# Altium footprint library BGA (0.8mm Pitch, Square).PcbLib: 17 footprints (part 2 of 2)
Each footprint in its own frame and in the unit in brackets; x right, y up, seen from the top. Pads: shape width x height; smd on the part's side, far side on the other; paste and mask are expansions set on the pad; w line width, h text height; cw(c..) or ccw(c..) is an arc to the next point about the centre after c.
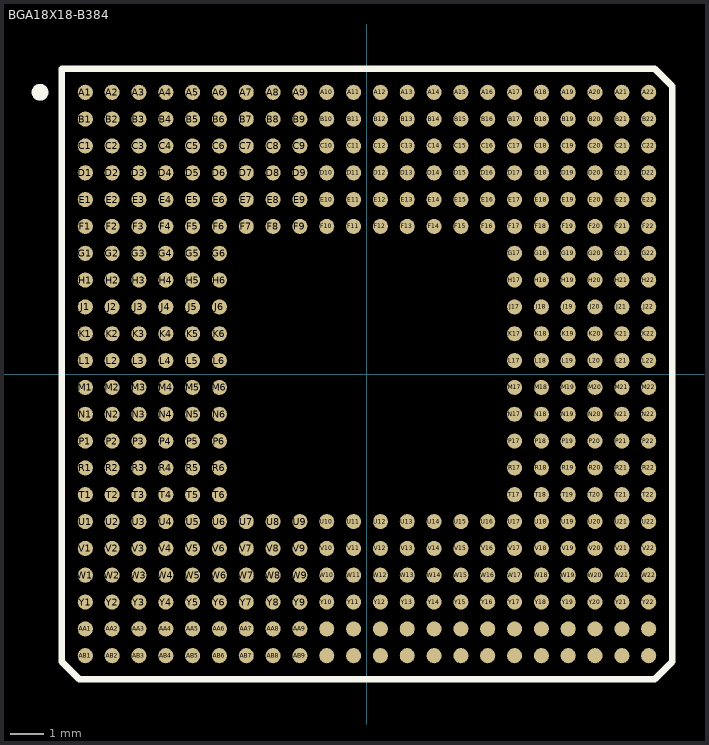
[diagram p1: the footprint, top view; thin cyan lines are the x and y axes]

## BGA18X18-B384 [mm]
pads (384):
  round 0.45 smd: A1(-8.4,8.4) A2(-7.6,8.4) A3(-6.8,8.4) A4(-6,8.4) A5(-5.2,8.4) A6(-4.4,8.4) A7(-3.6,8.4) A8(-2.8,8.4) A9(-2,8.4) A10(-1.2,8.4) A11(-0.4,8.4) A12(0.4,8.4) A13(1.2,8.4) A14(2,8.4) A15(2.8,8.4) A16(3.6,8.4) A17(4.4,8.4) A18(5.2,8.4) A19(6,8.4) A20(6.8,8.4) A21(7.6,8.4) A22(8.4,8.4) AA1(-8.4,-7.6) AA2(-7.6,-7.6) AA3(-6.8,-7.6) AA4(-6,-7.6) AA5(-5.2,-7.6) AA6(-4.4,-7.6) AA7(-3.6,-7.6) AA8(-2.8,-7.6) AA9(-2,-7.6) AA10(-1.2,-7.6) AA11(-0.4,-7.6) AA12(0.4,-7.6) AA13(1.2,-7.6) AA14(2,-7.6) AA15(2.8,-7.6) AA16(3.6,-7.6) AA17(4.4,-7.6) AA18(5.2,-7.6) AA19(6,-7.6) AA20(6.8,-7.6) AA21(7.6,-7.6) AA22(8.4,-7.6) AB1(-8.4,-8.4) AB2(-7.6,-8.4) AB3(-6.8,-8.4) AB4(-6,-8.4) AB5(-5.2,-8.4) AB6(-4.4,-8.4) AB7(-3.6,-8.4) AB8(-2.8,-8.4) AB9(-2,-8.4) AB10(-1.2,-8.4) AB11(-0.4,-8.4) AB12(0.4,-8.4) AB13(1.2,-8.4) AB14(2,-8.4) AB15(2.8,-8.4) AB16(3.6,-8.4) AB17(4.4,-8.4) AB18(5.2,-8.4) AB19(6,-8.4) AB20(6.8,-8.4) AB21(7.6,-8.4) AB22(8.4,-8.4) B1(-8.4,7.6) B2(-7.6,7.6) B3(-6.8,7.6) B4(-6,7.6) B5(-5.2,7.6) B6(-4.4,7.6) B7(-3.6,7.6) B8(-2.8,7.6) B9(-2,7.6) B10(-1.2,7.6) B11(-0.4,7.6) B12(0.4,7.6) B13(1.2,7.6) B14(2,7.6) B15(2.8,7.6) B16(3.6,7.6) B17(4.4,7.6) B18(5.2,7.6) B19(6,7.6) B20(6.8,7.6) B21(7.6,7.6) B22(8.4,7.6) C1(-8.4,6.8) C2(-7.6,6.8) C3(-6.8,6.8) C4(-6,6.8) C5(-5.2,6.8) C6(-4.4,6.8) C7(-3.6,6.8) C8(-2.8,6.8) C9(-2,6.8) C10(-1.2,6.8) C11(-0.4,6.8) C12(0.4,6.8) C13(1.2,6.8) C14(2,6.8) C15(2.8,6.8) C16(3.6,6.8) C17(4.4,6.8) C18(5.2,6.8) C19(6,6.8) C20(6.8,6.8) C21(7.6,6.8) C22(8.4,6.8) D1(-8.4,6) D2(-7.6,6) D3(-6.8,6) D4(-6,6) D5(-5.2,6) D6(-4.4,6) D7(-3.6,6) D8(-2.8,6) D9(-2,6) D10(-1.2,6) D11(-0.4,6) D12(0.4,6) D13(1.2,6) D14(2,6) D15(2.8,6) D16(3.6,6) D17(4.4,6) D18(5.2,6) D19(6,6) D20(6.8,6) D21(7.6,6) D22(8.4,6) E1(-8.4,5.2) E2(-7.6,5.2) E3(-6.8,5.2) E4(-6,5.2) E5(-5.2,5.2) E6(-4.4,5.2) E7(-3.6,5.2) E8(-2.8,5.2) E9(-2,5.2) E10(-1.2,5.2) E11(-0.4,5.2) E12(0.4,5.2) E13(1.2,5.2) E14(2,5.2) E15(2.8,5.2) E16(3.6,5.2) E17(4.4,5.2) E18(5.2,5.2) E19(6,5.2) E20(6.8,5.2) E21(7.6,5.2) E22(8.4,5.2) F1(-8.4,4.4) F2(-7.6,4.4) F3(-6.8,4.4) F4(-6,4.4) F5(-5.2,4.4) F6(-4.4,4.4) F7(-3.6,4.4) F8(-2.8,4.4) F9(-2,4.4) F10(-1.2,4.4) F11(-0.4,4.4) F12(0.4,4.4) F13(1.2,4.4) F14(2,4.4) F15(2.8,4.4) F16(3.6,4.4) F17(4.4,4.4) F18(5.2,4.4) F19(6,4.4) F20(6.8,4.4) F21(7.6,4.4) F22(8.4,4.4) G1(-8.4,3.6) G2(-7.6,3.6) G3(-6.8,3.6) G4(-6,3.6) G5(-5.2,3.6) G6(-4.4,3.6) G17(4.4,3.6) G18(5.2,3.6) G19(6,3.6) G20(6.8,3.6) G21(7.6,3.6) G22(8.4,3.6) H1(-8.4,2.8) H2(-7.6,2.8) H3(-6.8,2.8) H4(-6,2.8) H5(-5.2,2.8) H6(-4.4,2.8) H17(4.4,2.8) H18(5.2,2.8) H19(6,2.8) H20(6.8,2.8) H21(7.6,2.8) H22(8.4,2.8) J1(-8.4,2) J2(-7.6,2) J3(-6.8,2) J4(-6,2) J5(-5.2,2) J6(-4.4,2) J17(4.4,2) J18(5.2,2) J19(6,2) J20(6.8,2) J21(7.6,2) J22(8.4,2) K1(-8.4,1.2) K2(-7.6,1.2) K3(-6.8,1.2) K4(-6,1.2) K5(-5.2,1.2) K6(-4.4,1.2) K17(4.4,1.2) K18(5.2,1.2) K19(6,1.2) K20(6.8,1.2) K21(7.6,1.2) K22(8.4,1.2) L1(-8.4,0.4) L2(-7.6,0.4) L3(-6.8,0.4) L4(-6,0.4) L5(-5.2,0.4) L6(-4.4,0.4) L17(4.4,0.4) L18(5.2,0.4) L19(6,0.4) L20(6.8,0.4) L21(7.6,0.4) L22(8.4,0.4) M1(-8.4,-0.4) M2(-7.6,-0.4) M3(-6.8,-0.4) M4(-6,-0.4) M5(-5.2,-0.4) M6(-4.4,-0.4) M17(4.4,-0.4) M18(5.2,-0.4) M19(6,-0.4) M20(6.8,-0.4) M21(7.6,-0.4) M22(8.4,-0.4) N1(-8.4,-1.2) N2(-7.6,-1.2) N3(-6.8,-1.2) N4(-6,-1.2) N5(-5.2,-1.2) N6(-4.4,-1.2) N17(4.4,-1.2) N18(5.2,-1.2) N19(6,-1.2) N20(6.8,-1.2) N21(7.6,-1.2) N22(8.4,-1.2) P1(-8.4,-2) P2(-7.6,-2) P3(-6.8,-2) P4(-6,-2) P5(-5.2,-2) P6(-4.4,-2) P17(4.4,-2) P18(5.2,-2) P19(6,-2) P20(6.8,-2) P21(7.6,-2) P22(8.4,-2) R1(-8.4,-2.8) R2(-7.6,-2.8) R3(-6.8,-2.8) R4(-6,-2.8) R5(-5.2,-2.8) R6(-4.4,-2.8) R17(4.4,-2.8) R18(5.2,-2.8) R19(6,-2.8) R20(6.8,-2.8) R21(7.6,-2.8) R22(8.4,-2.8) T1(-8.4,-3.6) T2(-7.6,-3.6) T3(-6.8,-3.6) T4(-6,-3.6) T5(-5.2,-3.6) T6(-4.4,-3.6) T17(4.4,-3.6) T18(5.2,-3.6) T19(6,-3.6) T20(6.8,-3.6) T21(7.6,-3.6) T22(8.4,-3.6) U1(-8.4,-4.4) U2(-7.6,-4.4) U3(-6.8,-4.4) U4(-6,-4.4) U5(-5.2,-4.4) U6(-4.4,-4.4) U7(-3.6,-4.4) U8(-2.8,-4.4) U9(-2,-4.4) U10(-1.2,-4.4) U11(-0.4,-4.4) U12(0.4,-4.4) U13(1.2,-4.4) U14(2,-4.4) U15(2.8,-4.4) U16(3.6,-4.4) U17(4.4,-4.4) U18(5.2,-4.4) U19(6,-4.4) U20(6.8,-4.4) U21(7.6,-4.4) U22(8.4,-4.4) V1(-8.4,-5.2) V2(-7.6,-5.2) V3(-6.8,-5.2) V4(-6,-5.2) V5(-5.2,-5.2) V6(-4.4,-5.2) V7(-3.6,-5.2) V8(-2.8,-5.2) V9(-2,-5.2) V10(-1.2,-5.2) V11(-0.4,-5.2) V12(0.4,-5.2) V13(1.2,-5.2) V14(2,-5.2) V15(2.8,-5.2) V16(3.6,-5.2) V17(4.4,-5.2) V18(5.2,-5.2) V19(6,-5.2) V20(6.8,-5.2) V21(7.6,-5.2) V22(8.4,-5.2) W1(-8.4,-6) W2(-7.6,-6) W3(-6.8,-6) W4(-6,-6) W5(-5.2,-6) W6(-4.4,-6) W7(-3.6,-6) W8(-2.8,-6) W9(-2,-6) W10(-1.2,-6) W11(-0.4,-6) W12(0.4,-6) W13(1.2,-6) W14(2,-6) W15(2.8,-6) W16(3.6,-6) W17(4.4,-6) W18(5.2,-6) W19(6,-6) W20(6.8,-6) W21(7.6,-6) W22(8.4,-6) Y1(-8.4,-6.8) Y2(-7.6,-6.8) Y3(-6.8,-6.8) Y4(-6,-6.8) Y5(-5.2,-6.8) Y6(-4.4,-6.8) Y7(-3.6,-6.8) Y8(-2.8,-6.8) Y9(-2,-6.8) Y10(-1.2,-6.8) Y11(-0.4,-6.8) Y12(0.4,-6.8) Y13(1.2,-6.8) Y14(2,-6.8) Y15(2.8,-6.8) Y16(3.6,-6.8) Y17(4.4,-6.8) Y18(5.2,-6.8) Y19(6,-6.8) Y20(6.8,-6.8) Y21(7.6,-6.8) Y22(8.4,-6.8)
Top Overlay:
  circle w0.25: c-9.75,8.4 r0.125
  lines w0.2: -9.1,-8.584 -9.1,9.1 8.584,9.1 9.1,8.584 9.1,-8.584 8.584,-9.1 -8.584,-9.1 -9.1,-8.584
